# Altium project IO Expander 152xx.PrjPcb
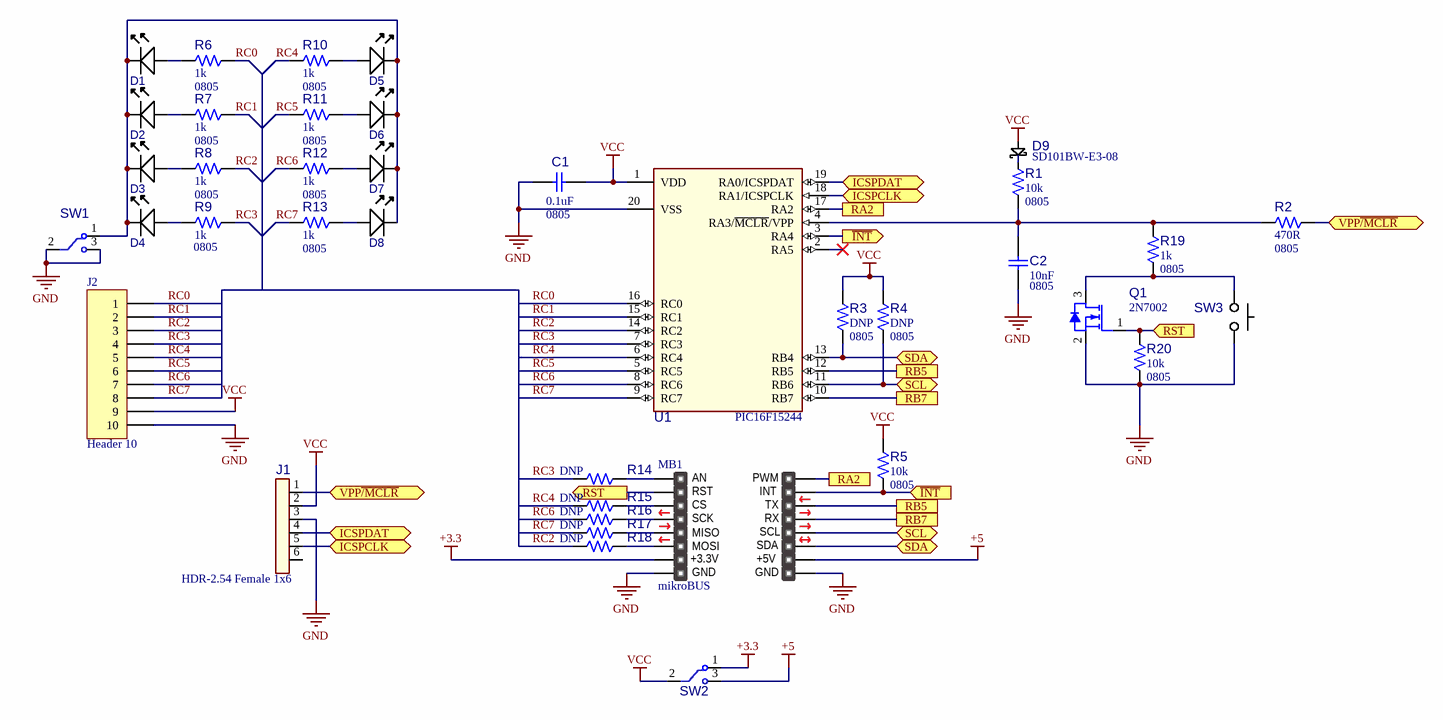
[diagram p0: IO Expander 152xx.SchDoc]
ProjectDrawnBy: Robert Perkel; ProjectEngineer: Robert Perkel; ProjectPartNumber: **; ProjectPCBAssyNumber: **; ProjectPCBNumber: **; ProjectRevisionART: **; ProjectRevisionASSY: **; ProjectRevisionFAB: **; ProjectRevisionSCH: **; ProjectTitle: I/O Expander - PIC16F15244
1 sheet, 39 parts. Net scope: flat (ports and power ports of the same name join across sheets).
Board file: IO Expander 152xx.PcbDoc

## Sheet IO Expander 152xx.SchDoc
size B; CompanyName: Microchip Technology Inc.; Organization: Microchip Technology; Address1: 2355 West Chandler Blvd.; Address2: Chandler, AZ  85224; Address4: USA; SheetNumber: 1; SheetTotal: 1; SheetTitle: **

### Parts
C1  value 0.1uF  Package: 0805  [RES_C_0805]  (hidden comment: Capacitor NP)
C2  value 10nF  Package: 0805  [RES_C_0805]  (hidden comment: Capacitor NP)
D1  LED  [0805 LED Package]  (value not drawn)
D2  LED  [0805 LED Package]  (value not drawn)
D3  LED  [0805 LED Package]  (value not drawn)
D4  LED  [0805 LED Package]  (value not drawn)
D5  LED  [0805 LED Package]  (value not drawn)
D6  LED  [0805 LED Package]  (value not drawn)
D7  LED  [0805 LED Package]  (value not drawn)
D8  LED  [0805 LED Package]  (value not drawn)
D9  SD101BW-E3-08  [SOD123]
J1  value HDR-2.54 Female 1x6  [HDR_F_2.54_1x6_RA]  (hidden comment: Header 1x6)
J2  Header 10  [HDR1X10]
MB1  mikroBUS  [mikroBUS - Large]  (no BOM)
Q1  value 2N7002  [SOT-23-3]  (hidden comment: Transistor MOS-N GSD)
R1  value 10k  Package: 0805  [RES_C_0805]  (hidden comment: Resistor)
R2  value 470R  Package: 0805  [RES_C_0805]  (hidden comment: Resistor)
R3  value DNP  Package: 0805  [RES_C_0805]  (hidden comment: Resistor)
R4  value DNP  Package: 0805  [RES_C_0805]  (hidden comment: Resistor)
R5  value 10k  Package: 0805  [RES_C_0805]  (hidden comment: Resistor)
R6  value 1k  Package: 0805  [RES_C_0805]  (hidden comment: Resistor)
R7  value 1k  Package: 0805  [RES_C_0805]  (hidden comment: Resistor)
R8  value 1k  Package: 0805  [RES_C_0805]  (hidden comment: Resistor)
R9  value 1k  Package: 0805  [RES_C_0805]  (hidden comment: Resistor)
R10  value 1k  Package: 0805  [RES_C_0805]  (hidden comment: Resistor)
R11  value 1k  Package: 0805  [RES_C_0805]  (hidden comment: Resistor)
R12  value 1k  Package: 0805  [RES_C_0805]  (hidden comment: Resistor)
R13  value 1k  Package: 0805  [RES_C_0805]  (hidden comment: Resistor)
R14  value DNP  [RES_C_0805]  (hidden comment: Resistor)
R15  value DNP  [RES_C_0805]  (hidden comment: Resistor)
R16  value DNP  [RES_C_0805]  (hidden comment: Resistor)
R17  value DNP  [RES_C_0805]  (hidden comment: Resistor)
R18  value DNP  [RES_C_0805]  (hidden comment: Resistor)
R19  value 1k  Package: 0805  [RES_C_0805]  (hidden comment: Resistor)
R20  value 10k  Package: 0805  [RES_C_0805]  (hidden comment: Resistor)
SW1  SWITCH SLIDE 3 Pin SPDT  [PCBComponent_1]  (value not drawn)
SW2  SMD Power Select  [3-Pad Select 0805]  (value not drawn)
SW3  SPST Switch  [PTS636]  (value not drawn)
U1  PIC16F15244  [SSOP-20_P0.65]

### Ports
ICSPCLK (bidir), ICSPDAT (bidir), RA2, RB5, RB7, RST (in), RST (out), SCL (bidir), SDA (bidir), VPP~{/MCLR} (bidir), ~{INT} (in), ~{INT} (out)

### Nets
+3.3: MB1.7(3.3V) SW2.1
+5: MB1.10(5V) SW2.3
GND: C1.1 C2.1 J1.3 J2.10 MB1.8(GND) MB1.9(GND) Q1.2(S) R20.1 SW1.2 SW1.3 SW3.2 U1.20(VSS)
VCC: C1.2 D9.Anode J1.2 J2.9 R3.2 R4.2 R5.2 SW2.2 U1.1(VDD)
~{INT}: MB1.15(INT) R5.1 U1.3(RA4) ; port ~{INT}
ICSPCLK: J1.5 U1.18(RA1/ICSPCLK) ; port ICSPCLK
ICSPDAT: J1.4 U1.19(RA0/ICSPDAT) ; port ICSPDAT
RA2: MB1.16(PWM) U1.17(RA2) ; port RA2
RB5: MB1.14(RX) U1.12(RB5) ; port RB5
RB7: MB1.13(TX) U1.10(RB7) ; port RB7
RC0: J2.1 R6.1 U1.16(RC0)
RC1: J2.2 R7.1 U1.15(RC1)
RC2: J2.3 R8.1 R18.2 U1.14(RC2)
RC3: J2.4 R9.1 R14.2 U1.7(RC3)
RC4: J2.5 R10.2 R15.2 U1.6(RC4)
RC5: J2.6 R11.2 U1.5(RC5)
RC6: J2.7 R12.2 R16.2 U1.8(RC6)
RC7: J2.8 R13.2 R17.2 U1.9(RC7)
RST: MB1.2(RST) Q1.1(G) R20.2 ; port RST
SCL: MB1.12(SCL) R4.1 U1.11(RB6) ; port SCL
SDA: MB1.11(SDA) R3.1 U1.13(RB4) ; port SDA
VPP~{/MCLR}: J1.1 R2.2 ; port VPP~{/MCLR}
NetC2_2: C2.2 R1.1 R2.1 R19.1 U1.4(RA3/~{MCLR}/VPP)
NetD1_Anode: D1.Anode R6.2
NetD1_Cathode: D1.Cathode D2.Cathode D3.Cathode D4.Cathode D5.Cathode D6.Cathode D7.Cathode D8.Cathode SW1.1
NetD2_Anode: D2.Anode R7.2
NetD3_Anode: D3.Anode R8.2
NetD4_Anode: D4.Anode R9.2
NetD5_Anode: D5.Anode R10.1
NetD6_Anode: D6.Anode R11.1
NetD7_Anode: D7.Anode R12.1
NetD8_Anode: D8.Anode R13.1
NetD9_Cathode: D9.Cathode R1.2
NetMB1_1: MB1.1(AN) R14.1
NetMB1_3: MB1.3(CS) R15.1
NetMB1_4: MB1.4(SCK) R16.1
NetMB1_5: MB1.5(MISO) R17.1
NetMB1_6: MB1.6(MOSI) R18.1
NetQ1_3: Q1.3(D) R19.2 SW3.1

Not connected (* = marked no-connect by the designer): J1 6; U1 2(RA5)*

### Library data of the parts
C1 C2 = CAP2000: Voltage: 10V
D9 = SC_Diode: Schottky Diode
J1 = CON0170: Manufacturer 1: Sullins; Manufacturer Part Number 1: PPPC061LGBN-RC; Description_: CON HDR-2.54 Female 1x6 Gold TH R/A; Dev Tools Status: Production; Owner: Ana Margeruseanu; Current: 3A; Populated: YES
J2 = Header 10: Header, 10-Pin
MB1 = mikroBUS compatible add-on board
Q1 = TRA1102: Transistor MOS; Manufacturer 1: Diodes Inc; Manufacturer Part Number 1: 2N7002-7-F; Description_: TRANS FET N-CH 2N7002-7-F 60V 170mA 370mW SOT-23-3; Dev Tools Status: Production; Type: FET; Current: 170mA; Drain to Source Voltage: 60V; Gate to Source Voltage: 20V; Power: 370mW; Owner: Adrian M (M91404); Populated: YES
R1 = RSMT0027: Tolerance: 5%; Description_: RES TKF 10k 5% 1/8W SMD 0805
R2 R6-R19 = RSMT0097: Tolerance: 5%
R3-R5 = RSMT0097: Tolerance: 5%; Voltage: 150V
R20 = RSMT0027: Tolerance: 5%; Description_: RES 10k 5% 1/8W SMD 0805
SW2 = SWITCH SLIDE 3 Pin SPDT
SW3 = SPST
U1 = PIC16F1524X SOIC-20_SSOP-20_PDIP-20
